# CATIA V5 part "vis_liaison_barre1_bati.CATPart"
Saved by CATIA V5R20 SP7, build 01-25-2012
Part number: skl_vis_liaison_barre1_bati
Bounding box of the stored display mesh (mm): x -7 to 0, y 25.773 to 25.773, z 10.42 to 10.42
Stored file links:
  J:\IFMA\IAO\système avant mef\vis_liaison_barre1_bati.CATPart
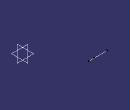
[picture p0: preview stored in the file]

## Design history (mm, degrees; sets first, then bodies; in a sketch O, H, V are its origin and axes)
Body1 (main body)
  Point1 "Point.Eprim": stored without definition
  Point2 "Point.E": stored without definition
  Line1: type PtPt, FirstPoint Point1, SecondPoint Point2
  Point3 "Point_E_vis": stored without definition
  Point4 "Point.E": stored without definition
  Line2: type PtPt, FirstPoint Point3, SecondPoint Point4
